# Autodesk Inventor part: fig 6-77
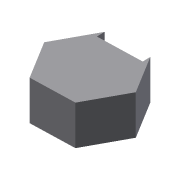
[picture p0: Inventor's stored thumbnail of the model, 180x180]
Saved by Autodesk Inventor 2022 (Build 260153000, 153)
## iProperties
Created: 2009-03
Part Number: fig 6-77
Document SubType Name: Modeling
Designer: Sham
Density: 1 g/cm^3
Material: Generic
Appearance: Default
Author: Sham
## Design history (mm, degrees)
sketch "Sketch5"
  geometry: L1 (-5.929, 9.627)-(5.372, 9.948); L2 (5.372, 9.948)-(11.301, 0.321); L3 (11.301, 0.321)-(5.929, -9.627); L4 (5.929, -9.627)-(-5.372, -9.948); L5 (-5.372, -9.948)-(-11.301, -0.321); L6 (-11.301, -0.321)-(-5.929, 9.627); 1 further point
  constraints: 12 end point, 13 other
extrude "Extrusion3" new body sketch "Sketch5" distance "d13" = 10; taper "d14" = 0 deg
thicken "Thicken2" dims "d15" = 2, "d16" = 2
body "Solid4"
